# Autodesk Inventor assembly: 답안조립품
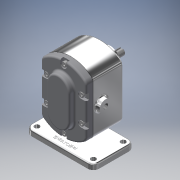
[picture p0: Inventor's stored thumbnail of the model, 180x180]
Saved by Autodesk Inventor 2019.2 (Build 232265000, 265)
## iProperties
Created: 2019-03
Part Number: 답안조립품
Material: 일반
Document SubType Name: Assembly
Designer: User
Author: User
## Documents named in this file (11)
- C:\Users\User\Desktop\490307V1034\답안조립품.iam
- C:\Users\User\Desktop\490307V1034\본체.ipt
- C:\Users\User\Desktop\490307V1034\베어링부시.ipt
- C:\Users\User\Desktop\490307V1034\개스킷.ipt
- C:\Users\User\Desktop\490307V1034\커버.ipt
- C:\Users\User\Desktop\490307V1034\볼트 M5.ipt
- C:\Users\User\Desktop\490307V1034\메인축.ipt
- C:\Users\User\Desktop\490307V1034\서브축.ipt
- C:\Users\User\Desktop\490307V1034\스퍼기어.ipt
- C:\Users\User\Desktop\490307V1034\키 6 x 6 x 18.ipt
- C:\Users\User\Desktop\490307V1034\오일 실 16 28 7.ipt
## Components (1 placed, 1 different names)
1. 개스킷:1
